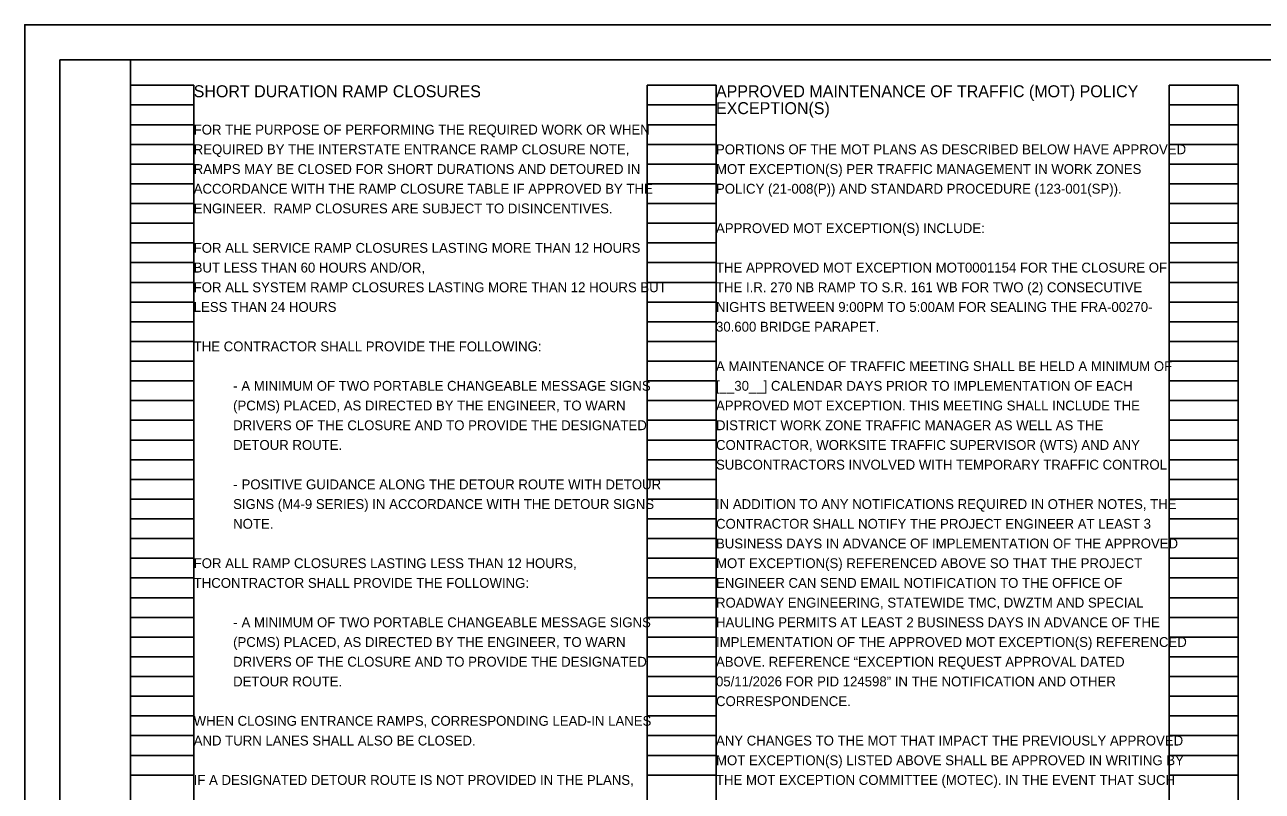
# Model space of a CAD drawing. Extents: x 0 to 34, y 0 to 22.
# Drawn here: x 0 to 17.58, y 11.11 to 22 of the extents above; entities that cross this region are included whole.
import ezdxf

# ---------------------------------------------------------------- set-up
doc = ezdxf.new("R2010")
doc.units = 0
for name, color, linetype in [('SH_Border', 7, 'Continuous'), ('SH_Cut_Line', 7, 'Continuous'), ('SH_Data', 7, 'Continuous'), ('SH_Text', 7, 'Continuous')]:
    doc.layers.add(name, color=color, linetype=linetype)

msp = doc.modelspace()

# ---------------------------------------------------------------- linework, layer by layer
at = {"layer": 'SH_Border'}
for points in [[(0.5, 21.5), (1.5, 21.5), (1.5, 0.5), (0.5, 0.5)], [(1.5, 21.5), (33.5, 21.5), (33.5, 0.5), (1.5, 0.5)]]:
    msp.add_lwpolyline(points, close=True, dxfattribs=at)
at = {"layer": 'SH_Cut_Line'}
msp.add_lwpolyline([(0, 0), (34, 0), (34, 22), (0, 22)], close=True, dxfattribs=at)
at = {"layer": 'SH_Data'}
for p, q in [((1.5, 0.98), (1.5, 21.14)), ((1.5, 21.14), (2.4, 21.14)), ((2.4, 0.98), (2.4, 21.14)), ((8.84, 0.98), (8.84, 21.14)), ((8.84, 21.14), (9.82, 21.14)), ((9.82, 0.98), (9.82, 21.14)), ((16.26, 0.98), (16.26, 21.14)), ((16.26, 21.14), (17.24, 21.14)), ((17.24, 0.98), (17.24, 21.14)), ((1.5, 20.86), (2.4, 20.86)), ((8.84, 20.86), (9.82, 20.86)), ((16.26, 20.86), (17.24, 20.86)), ((1.5, 20.58), (2.4, 20.58)), ((8.84, 20.58), (9.82, 20.58)), ((16.26, 20.58), (17.24, 20.58)), ((1.5, 20.3), (2.4, 20.3)), ((8.84, 20.3), (9.82, 20.3)), ((16.26, 20.3), (17.24, 20.3)), ((1.5, 20.02), (2.4, 20.02)), ((8.84, 20.02), (9.82, 20.02)), ((16.26, 20.02), (17.24, 20.02)), ((1.5, 19.74), (2.4, 19.74)), ((8.84, 19.74), (9.82, 19.74)), ((16.26, 19.74), (17.24, 19.74)), ((1.5, 19.46), (2.4, 19.46)), ((8.84, 19.46), (9.82, 19.46)), ((16.26, 19.46), (17.24, 19.46)), ((1.5, 19.18), (2.4, 19.18)), ((8.84, 19.18), (9.82, 19.18)), ((16.26, 19.18), (17.24, 19.18)), ((1.5, 18.9), (2.4, 18.9)), ((8.84, 18.9), (9.82, 18.9)), ((16.26, 18.9), (17.24, 18.9)), ((1.5, 18.62), (2.4, 18.62)), ((8.84, 18.62), (9.82, 18.62)), ((16.26, 18.62), (17.24, 18.62)), ((1.5, 18.34), (2.4, 18.34)), ((8.84, 18.34), (9.82, 18.34)), ((16.26, 18.34), (17.24, 18.34)), ((1.5, 18.06), (2.4, 18.06)), ((8.84, 18.06), (9.82, 18.06)), ((16.26, 18.06), (17.24, 18.06)), ((1.5, 17.78), (2.4, 17.78)), ((8.84, 17.78), (9.82, 17.78)), ((16.26, 17.78), (17.24, 17.78)), ((1.5, 17.5), (2.4, 17.5)), ((8.84, 17.5), (9.82, 17.5)), ((16.26, 17.5), (17.24, 17.5)), ((1.5, 17.22), (2.4, 17.22)), ((8.84, 17.22), (9.82, 17.22)), ((16.26, 17.22), (17.24, 17.22)), ((1.5, 16.94), (2.4, 16.94)), ((8.84, 16.94), (9.82, 16.94)), ((16.26, 16.94), (17.24, 16.94)), ((1.5, 16.66), (2.4, 16.66)), ((8.84, 16.66), (9.82, 16.66)), ((16.26, 16.66), (17.24, 16.66)), ((1.5, 16.38), (2.4, 16.38)), ((8.84, 16.38), (9.82, 16.38)), ((16.26, 16.38), (17.24, 16.38)), ((1.5, 16.1), (2.4, 16.1)), ((8.84, 16.1), (9.82, 16.1)), ((16.26, 16.1), (17.24, 16.1)), ((1.5, 15.82), (2.4, 15.82)), ((8.84, 15.82), (9.82, 15.82)), ((16.26, 15.82), (17.24, 15.82)), ((1.5, 15.54), (2.4, 15.54)), ((8.84, 15.54), (9.82, 15.54)), ((16.26, 15.54), (17.24, 15.54)), ((1.5, 15.26), (2.4, 15.26)), ((8.84, 15.26), (9.82, 15.26)), ((16.26, 15.26), (17.24, 15.26)), ((1.5, 14.98), (2.4, 14.98)), ((8.84, 14.98), (9.82, 14.98)), ((16.26, 14.98), (17.24, 14.98)), ((1.5, 14.7), (2.4, 14.7)), ((8.84, 14.7), (9.82, 14.7)), ((16.26, 14.7), (17.24, 14.7)), ((1.5, 14.42), (2.4, 14.42)), ((8.84, 14.42), (9.82, 14.42)), ((16.26, 14.42), (17.24, 14.42)), ((1.5, 14.14), (2.4, 14.14)), ((8.84, 14.14), (9.82, 14.14)), ((16.26, 14.14), (17.24, 14.14)), ((1.5, 13.86), (2.4, 13.86)), ((8.84, 13.86), (9.82, 13.86)), ((16.26, 13.86), (17.24, 13.86)), ((1.5, 13.58), (2.4, 13.58)), ((8.84, 13.58), (9.82, 13.58)), ((16.26, 13.58), (17.24, 13.58)), ((1.5, 13.3), (2.4, 13.3)), ((8.84, 13.3), (9.82, 13.3)), ((16.26, 13.3), (17.24, 13.3)), ((1.5, 13.02), (2.4, 13.02)), ((8.84, 13.02), (9.82, 13.02)), ((16.26, 13.02), (17.24, 13.02)), ((1.5, 12.74), (2.4, 12.74)), ((8.84, 12.74), (9.82, 12.74)), ((16.26, 12.74), (17.24, 12.74)), ((1.5, 12.46), (2.4, 12.46)), ((8.84, 12.46), (9.82, 12.46)), ((16.26, 12.46), (17.24, 12.46)), ((1.5, 12.18), (2.4, 12.18)), ((8.84, 12.18), (9.82, 12.18)), ((16.26, 12.18), (17.24, 12.18)), ((1.5, 11.9), (2.4, 11.9)), ((8.84, 11.9), (9.82, 11.9)), ((16.26, 11.9), (17.24, 11.9)), ((1.5, 11.62), (2.4, 11.62)), ((8.84, 11.62), (9.82, 11.62)), ((16.26, 11.62), (17.24, 11.62)), ((1.5, 11.34), (2.4, 11.34)), ((8.84, 11.34), (9.82, 11.34)), ((16.26, 11.34), (17.24, 11.34))]:
    msp.add_line(p, q, dxfattribs=at)

# ---------------------------------------------------------------- texts
at = {"layer": 'SH_Text'}
for s, height, p in [('SHORT DURATION RAMP CLOSURES', 0.17, (2.4, 20.97)), ('APPROVED MAINTENANCE OF TRAFFIC (MOT) POLICY ', 0.17, (9.82, 20.97)), ('EXCEPTION(S)', 0.17, (9.82, 20.73)), ('FOR THE PURPOSE OF PERFORMING THE REQUIRED WORK OR WHEN ', 0.14, (2.4, 20.44)), ('REQUIRED BY THE INTERSTATE ENTRANCE RAMP CLOSURE NOTE, ', 0.14, (2.4, 20.16)), ('PORTIONS OF THE MOT PLANS AS DESCRIBED BELOW HAVE APPROVED ', 0.14, (9.82, 20.16)), ('RAMPS MAY BE CLOSED FOR SHORT DURATIONS AND DETOURED IN ', 0.14, (2.4, 19.88)), ('MOT EXCEPTION(S) PER TRAFFIC MANAGEMENT IN WORK ZONES ', 0.14, (9.82, 19.88)), ('ACCORDANCE WITH THE RAMP CLOSURE TABLE IF APPROVED BY THE ', 0.14, (2.4, 19.6)), ('POLICY (21-008(P)) AND STANDARD PROCEDURE (123-001(SP)). ', 0.14, (9.82, 19.6)), ('ENGINEER.  RAMP CLOSURES ARE SUBJECT TO DISINCENTIVES.', 0.14, (2.4, 19.32)), ('APPROVED MOT EXCEPTION(S) INCLUDE:', 0.14, (9.82, 19.04)), ('FOR ALL SERVICE RAMP CLOSURES LASTING MORE THAN 12 HOURS ', 0.14, (2.4, 18.76)), ('BUT LESS THAN 60 HOURS AND/OR,', 0.14, (2.4, 18.48)), ('THE APPROVED MOT EXCEPTION MOT0001154 FOR THE CLOSURE OF ', 0.14, (9.82, 18.48)), ('FOR ALL SYSTEM RAMP CLOSURES LASTING MORE THAN 12 HOURS BUT ', 0.14, (2.4, 18.2)), ('THE I.R. 270 NB RAMP TO S.R. 161 WB FOR TWO (2) CONSECUTIVE ', 0.14, (9.82, 18.2)), ('LESS THAN 24 HOURS ', 0.14, (2.4, 17.92)), ('NIGHTS BETWEEN 9:00PM TO 5:00AM FOR SEALING THE FRA-00270-', 0.14, (9.82, 17.92)), ('30.600 BRIDGE PARAPET. ', 0.14, (9.82, 17.64)), ('THE CONTRACTOR SHALL PROVIDE THE FOLLOWING:', 0.14, (2.4, 17.36)), ('A MAINTENANCE OF TRAFFIC MEETING SHALL BE HELD A MINIMUM OF ', 0.14, (9.82, 17.08)), ('A MINIMUM OF TWO PORTABLE CHANGEABLE MESSAGE SIGNS ', 0.14, (3.077, 16.8)), ('[__30__] CALENDAR DAYS PRIOR TO IMPLEMENTATION OF EACH ', 0.14, (9.82, 16.8)), ('- ', 0.14, (2.96, 16.8)), ('(PCMS) PLACED, AS DIRECTED BY THE ENGINEER, TO WARN ', 0.14, (2.96, 16.52)), ('APPROVED MOT EXCEPTION. THIS MEETING SHALL INCLUDE THE ', 0.14, (9.82, 16.52)), ('DRIVERS OF THE CLOSURE AND TO PROVIDE THE DESIGNATED ', 0.14, (2.96, 16.24)), ('DISTRICT WORK ZONE TRAFFIC MANAGER AS WELL AS THE ', 0.14, (9.82, 16.24)), ('DETOUR ROUTE. ', 0.14, (2.96, 15.96)), ('CONTRACTOR, WORKSITE TRAFFIC SUPERVISOR (WTS) AND ANY ', 0.14, (9.82, 15.96)), ('SUBCONTRACTORS INVOLVED WITH TEMPORARY TRAFFIC CONTROL. ', 0.14, (9.82, 15.68)), (' POSITIVE GUIDANCE ALONG THE DETOUR ROUTE WITH DETOUR ', 0.14, (3.028, 15.4)), ('-', 0.14, (2.96, 15.4)), ('SIGNS (M4-9 SERIES) IN ACCORDANCE WITH THE DETOUR SIGNS ', 0.14, (2.96, 15.12)), ('IN ADDITION TO ANY NOTIFICATIONS REQUIRED IN OTHER NOTES, THE ', 0.14, (9.82, 15.12)), ('NOTE.  ', 0.14, (2.96, 14.84)), ('CONTRACTOR SHALL NOTIFY THE PROJECT ENGINEER AT LEAST 3 ', 0.14, (9.82, 14.84)), ('BUSINESS DAYS IN ADVANCE OF IMPLEMENTATION OF THE APPROVED ', 0.14, (9.82, 14.56)), ('FOR ALL RAMP CLOSURES LASTING LESS THAN 12 HOURS, ', 0.14, (2.4, 14.28)), ('MOT EXCEPTION(S) REFERENCED ABOVE SO THAT THE PROJECT ', 0.14, (9.82, 14.28)), ('THCONTRACTOR SHALL PROVIDE THE FOLLOWING:', 0.14, (2.4, 14)), ('ENGINEER CAN SEND EMAIL NOTIFICATION TO THE OFFICE OF ', 0.14, (9.82, 14)), ('ROADWAY ENGINEERING, STATEWIDE TMC, DWZTM AND SPECIAL ', 0.14, (9.82, 13.72)), (' A MINIMUM OF TWO PORTABLE CHANGEABLE MESSAGE SIGNS ', 0.14, (3.028, 13.44)), ('HAULING PERMITS AT LEAST 2 BUSINESS DAYS IN ADVANCE OF THE ', 0.14, (9.82, 13.44)), ('-', 0.14, (2.96, 13.44)), ('(PCMS) PLACED, AS DIRECTED BY THE ENGINEER, TO WARN ', 0.14, (2.96, 13.16)), ('IMPLEMENTATION OF THE APPROVED MOT EXCEPTION(S) REFERENCED ', 0.14, (9.82, 13.16)), ('DRIVERS OF THE CLOSURE AND TO PROVIDE THE DESIGNATED ', 0.14, (2.96, 12.88)), ('ABOVE. REFERENCE “EXCEPTION REQUEST APPROVAL DATED', 0.14, (9.82, 12.88)), ('DETOUR ROUTE.  ', 0.14, (2.96, 12.6)), ('05/11/2026 FOR PID 124598” IN THE NOTIFICATION AND OTHER ', 0.14, (9.82, 12.6)), ('CORRESPONDENCE. ', 0.14, (9.82, 12.32)), ('WHEN CLOSING ENTRANCE RAMPS, CORRESPONDING LEAD-IN LANES ', 0.14, (2.4, 12.04)), ('AND TURN LANES SHALL ALSO BE CLOSED.', 0.14, (2.4, 11.76)), ('ANY CHANGES TO THE MOT THAT IMPACT THE PREVIOUSLY APPROVED ', 0.14, (9.82, 11.76)), ('MOT EXCEPTION(S) LISTED ABOVE SHALL BE APPROVED IN WRITING BY ', 0.14, (9.82, 11.48)), ('IF A DESIGNATED DETOUR ROUTE IS NOT PROVIDED IN THE PLANS, ', 0.14, (2.4, 11.2)), ('THE MOT EXCEPTION COMMITTEE (MOTEC). IN THE EVENT THAT SUCH ', 0.14, (9.82, 11.2))]:
    msp.add_text(s, height=height, dxfattribs=at).set_placement(p)

doc.saveas('drawing.dxf')
